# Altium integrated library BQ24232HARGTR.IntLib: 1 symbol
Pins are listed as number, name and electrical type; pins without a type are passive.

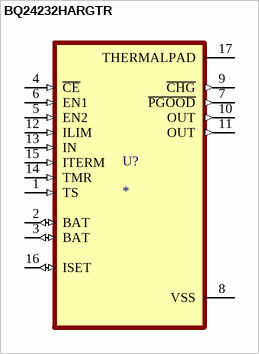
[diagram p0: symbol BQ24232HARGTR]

## BQ24232HARGTR
designator U?
MP: BQ24232HARGTR
footprint QFN50P300X300X100-17N
pins: 1 TS (in), 2 BAT (io), 3 BAT (io), 4 ~{CE} (in), 5 EN2 (in), 6 EN1 (in), 7 ~{PGOOD} (out), 8 VSS (power), 9 ~{CHG} (out), 10 OUT (out), 11 OUT (out), 12 ILIM (in), 13 IN (in), 14 TMR (in), 15 ITERM (in), 16 ISET (io), 17 THERMALPAD (power)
